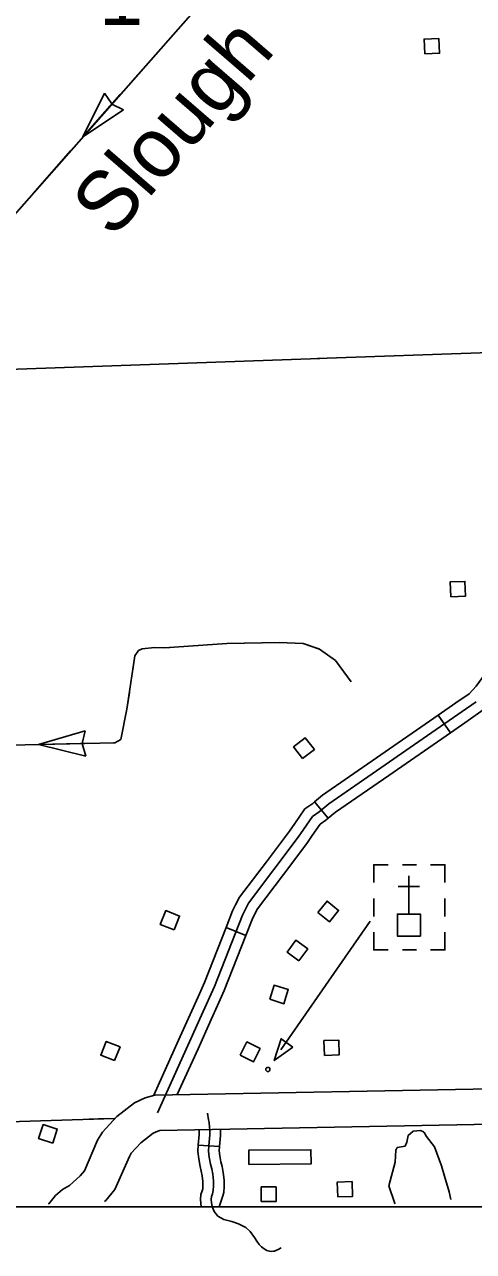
# Model space of a CAD drawing. Extents: x 1671357 to 13005564, y 567358 to 14261451.
# Drawn here: x 12758262.26 to 12758268.24, y 14259853.37 to 14259869.74 of the extents above; entities that cross this region are included whole.
import ezdxf

# ---------------------------------------------------------------- set-up
doc = ezdxf.new("R2010")
doc.units = 0
for name, color, linetype in [('10', 7, 'Continuous'), ('2', 7, 'Continuous'), ('31', 7, 'Continuous'), ('32', 7, 'Continuous'), ('35', 7, 'Continuous'), ('43', 7, 'Continuous'), ('5', 7, 'Continuous'), ('56', 7, 'Continuous')]:
    doc.layers.add(name, color=color, linetype=linetype)

msp = doc.modelspace()

# ---------------------------------------------------------------- linework, layer by layer
at = {"layer": '10'}
for points in [[(12758263.324, 14259854.033), (12758263.343, 14259854.05), (12758263.463, 14259854.196), (12758263.655, 14259854.637), (12758263.68, 14259854.679), (12758263.808, 14259854.82), (12758263.973, 14259854.945), (12758264.036, 14259854.975), (12758264.063, 14259854.983), (12758268.719, 14259855.072), (12758274.49, 14259855.167), (12758274.715, 14259855.191), (12758274.93, 14259855.304), (12758275.071, 14259855.431), (12758275.572, 14259857.551)], [(12758268.71, 14259855.545), (12758263.993, 14259855.456), (12758263.866, 14259855.419), (12758263.724, 14259855.351), (12758263.488, 14259855.171), (12758263.296, 14259854.961), (12758263.232, 14259854.852), (12758263.055, 14259854.446), (12758263, 14259854.379), (12758262.855, 14259854.249), (12758262.764, 14259854.197), (12758262.668, 14259854.114), (12758262.581, 14259854.005), (12758262.579, 14259854.001)]]:
    msp.add_lwpolyline(points, dxfattribs=at)
at = {"layer": '2'}
msp.add_line((12758241.074, 14259853.963), (12758347.684, 14259853.963), dxfattribs=at)
at = {"layer": '31'}
for p, q in [((12758267.772, 14259860.525), (12758267.934, 14259860.292)), ((12758266.125, 14259859.369), (12758266.307, 14259859.151)), ((12758265.708, 14259858.399), (12758265.708, 14259858.399)), ((12758265.208, 14259857.586), (12758264.944, 14259857.69))]:
    msp.add_line(p, q, dxfattribs=at)
for points in [[(12758268.439, 14259861.15), (12758268.419, 14259861.107), (12758268.277, 14259860.913), (12758268.183, 14259860.813), (12758268.009, 14259860.689), (12758267.772, 14259860.525)], [(12758267.934, 14259860.292), (12758268.172, 14259860.457), (12758268.371, 14259860.598), (12758268.495, 14259860.731), (12758268.663, 14259860.96), (12758268.695, 14259861.027)], [(12758268.277, 14259860.706), (12758268.09, 14259860.573), (12758266.316, 14259859.344), (12758266.187, 14259859.237), (12758266.097, 14259859.172), (12758265.977, 14259858.998), (12758265.907, 14259858.897), (12758265.243, 14259858.019), (12758265.197, 14259857.93), (12758265.162, 14259857.856), (12758264.788, 14259856.905), (12758264.617, 14259856.522)], [(12758267.772, 14259860.525), (12758266.95, 14259859.956)], [(12758267.934, 14259860.292), (12758267.112, 14259859.722)], [(12758266.95, 14259859.956), (12758266.23, 14259859.457), (12758266.125, 14259859.369)], [(12758267.112, 14259859.722), (12758266.402, 14259859.231), (12758266.307, 14259859.151)], [(12758265.481, 14259858.57), (12758265.791, 14259858.98), (12758265.86, 14259859.079), (12758265.994, 14259859.274), (12758266.1, 14259859.349), (12758266.125, 14259859.369)], [(12758266.307, 14259859.151), (12758266.274, 14259859.124), (12758266.2, 14259859.071), (12758266.094, 14259858.918), (12758266.022, 14259858.814), (12758265.708, 14259858.399)], [(12758264.944, 14259857.69), (12758265.031, 14259857.913), (12758265.069, 14259857.993), (12758265.122, 14259858.095), (12758265.481, 14259858.57)], [(12758265.708, 14259858.399), (12758265.363, 14259857.943), (12758265.324, 14259857.867), (12758265.292, 14259857.8), (12758265.208, 14259857.586)], [(12758264.944, 14259857.69), (12758264.657, 14259856.96), (12758264.572, 14259856.768)], [(12758265.208, 14259857.586), (12758264.919, 14259856.85), (12758264.831, 14259856.652)], [(12758264.572, 14259856.768), (12758264.488, 14259856.58)], [(12758264.311, 14259856.189), (12758264.488, 14259856.58)], [(12758264.831, 14259856.652), (12758264.747, 14259856.464)], [(12758264.028, 14259855.219), (12758264.617, 14259856.522)], [(12758264.57, 14259856.072), (12758264.747, 14259856.463)], [(12758263.979, 14259855.455), (12758264.311, 14259856.189)], [(12758264.293, 14259855.461), (12758264.57, 14259856.072)]]:
    msp.add_lwpolyline(points, dxfattribs=at)
at = {"layer": '32'}
msp.add_line((12758264.856, 14259854.768), (12758264.573, 14259854.786), dxfattribs=at)
for points in [[(12758265.68, 14259853.415), (12758265.639, 14259853.395), (12758265.608, 14259853.38), (12758265.591, 14259853.374), (12758265.576, 14259853.371), (12758265.551, 14259853.368), (12758265.521, 14259853.371), (12758265.488, 14259853.382), (12758265.451, 14259853.402), (12758265.416, 14259853.431), (12758265.386, 14259853.462), (12758265.356, 14259853.506), (12758265.322, 14259853.554), (12758265.267, 14259853.633), (12758265.208, 14259853.686), (12758265.161, 14259853.712), (12758265.109, 14259853.737), (12758265.019, 14259853.767), (12758264.913, 14259853.795), (12758264.836, 14259853.837), (12758264.784, 14259853.9), (12758264.76, 14259853.967), (12758264.749, 14259854.018), (12758264.745, 14259854.061), (12758264.749, 14259854.1), (12758264.761, 14259854.136), (12758264.772, 14259854.18), (12758264.777, 14259854.242), (12758264.778, 14259854.31), (12758264.767, 14259854.399), (12758264.752, 14259854.472), (12758264.736, 14259854.533), (12758264.719, 14259854.625), (12758264.71, 14259854.706), (12758264.715, 14259854.779), (12758264.727, 14259854.924), (12758264.728, 14259854.99), (12758264.725, 14259855.028), (12758264.719, 14259855.089), (12758264.71, 14259855.123), (12758264.696, 14259855.213)], [(12758264.573, 14259854.786), (12758264.573, 14259854.789), (12758264.585, 14259854.931), (12758264.586, 14259854.993)], [(12758264.856, 14259854.768), (12758264.869, 14259854.916), (12758264.871, 14259854.999)], [(12758264.611, 14259853.963), (12758264.602, 14259854.063), (12758264.609, 14259854.129), (12758264.624, 14259854.176), (12758264.632, 14259854.204), (12758264.635, 14259854.248), (12758264.636, 14259854.302), (12758264.626, 14259854.376), (12758264.614, 14259854.441), (12758264.598, 14259854.501), (12758264.579, 14259854.604), (12758264.568, 14259854.703), (12758264.573, 14259854.786)], [(12758264.854, 14259853.963), (12758264.897, 14259854.097), (12758264.913, 14259854.157), (12758264.919, 14259854.235), (12758264.92, 14259854.318), (12758264.907, 14259854.422), (12758264.891, 14259854.504), (12758264.875, 14259854.564), (12758264.86, 14259854.646), (12758264.853, 14259854.71), (12758264.856, 14259854.768)]]:
    msp.add_lwpolyline(points, dxfattribs=at)
at = {"layer": '35'}
for points in [[(12758267.575, 14259854.964), (12758267.537, 14259854.982), (12758267.438, 14259854.974), (12758267.372, 14259854.918), (12758267.353, 14259854.826), (12758267.331, 14259854.772), (12758267.227, 14259854.755), (12758267.209, 14259854.722), (12758267.197, 14259854.56), (12758267.114, 14259854.243), (12758267.195, 14259854.009), (12758267.191, 14259854.005)], [(12758267.939, 14259854.063), (12758267.918, 14259854.162), (12758267.854, 14259854.373), (12758267.816, 14259854.512), (12758267.721, 14259854.765), (12758267.617, 14259854.901), (12758267.585, 14259854.957), (12758267.575, 14259854.964)]]:
    msp.add_lwpolyline(points, dxfattribs=at)
at = {"layer": '43'}
for p, q in [((12758263.036, 14259868.246), (12758263.325, 14259868.828)), ((12758263.325, 14259868.828), (12758263.421, 14259868.684)), ((12758263.578, 14259868.606), (12758263.423, 14259868.683)), ((12758263.036, 14259868.246), (12758263.578, 14259868.606)), ((12758262.442, 14259860.134), (12758263.066, 14259860.316)), ((12758263.066, 14259860.316), (12758263.025, 14259860.148)), ((12758262.442, 14259860.134), (12758263.073, 14259859.98)), ((12758263.073, 14259859.98), (12758263.025, 14259860.146))]:
    msp.add_line(p, q, dxfattribs=at)
for points in [[(12758266.589, 14259872.281), (12758260.694, 14259865.585), (12758260.462, 14259865.405), (12758260.203, 14259865.244), (12758259.962, 14259865.138), (12758259.827, 14259865.101), (12758259.106, 14259865.033), (12758258.777, 14259865.016), (12758257.851, 14259865.054), (12758257.587, 14259865.116), (12758257.47, 14259865.153), (12758253.89, 14259867.232), (12758253.044, 14259867.635), (12758251.551, 14259868.43), (12758251.309, 14259868.466), (12758251.009, 14259868.39), (12758239.909, 14259866.397), (12758239.657, 14259866.374), (12758239.504, 14259866.384), (12758239.465, 14259866.393)], [(12758264.193, 14259869.559), (12758263.697, 14259868.996)], [(12758263.532, 14259868.809), (12758263.036, 14259868.246)], [(12758262.871, 14259868.058), (12758262.623, 14259867.776)], [(12758262.623, 14259867.776), (12758262.376, 14259867.495)], [(12758266.611, 14259860.97), (12758266.401, 14259861.256), (12758266.19, 14259861.406), (12758265.973, 14259861.481), (12758265.653, 14259861.495), (12758264.952, 14259861.483), (12758264.122, 14259861.424), (12758263.988, 14259861.428), (12758263.824, 14259861.41), (12758263.777, 14259861.388), (12758263.729, 14259861.317), (12758263.623, 14259860.608), (12758263.54, 14259860.202), (12758263.462, 14259860.157), (12758255.478, 14259859.977)], [(12758265.191, 14259861.487), (12758264.952, 14259861.483), (12758264.443, 14259861.447)], [(12758266.179, 14259861.41), (12758265.973, 14259861.481), (12758265.653, 14259861.495), (12758265.441, 14259861.491)], [(12758264.193, 14259861.429), (12758264.122, 14259861.424), (12758263.988, 14259861.428), (12758263.824, 14259861.41), (12758263.777, 14259861.388), (12758263.729, 14259861.317), (12758263.693, 14259861.078)], [(12758266.611, 14259860.97), (12758266.401, 14259861.256), (12758266.384, 14259861.268)], [(12758263.656, 14259860.831), (12758263.623, 14259860.608), (12758263.54, 14259860.202), (12758263.462, 14259860.157), (12758263.441, 14259860.157)], [(12758263.191, 14259860.151), (12758262.442, 14259860.134)]]:
    msp.add_lwpolyline(points, dxfattribs=at)
at = {"layer": '5'}
for points in [[(12758266.162, 14259865.286), (12758268.459, 14259865.366), (12758270.694, 14259865.434)], [(12758259.508, 14259865.053), (12758266.196, 14259865.287)], [(12758266.162, 14259865.286), (12758266.196, 14259865.287)], [(12758263.457, 14259855.144), (12758258.808, 14259854.995)], [(12758263.359, 14259855.141), (12758263.12, 14259855.133)]]:
    msp.add_lwpolyline(points, dxfattribs=at)
at = {"layer": '56'}
for p, q in [((12758267.483, 14259858.529), (12758267.294, 14259858.529)), ((12758267.381, 14259858.382), (12758267.381, 14259857.872)), ((12758267.239, 14259858.24), (12758267.524, 14259858.24)), ((12758266.914, 14259858.077), (12758266.914, 14259857.841)), ((12758267.861, 14259857.961), (12758267.861, 14259858.077)), ((12758267.861, 14259857.961), (12758267.861, 14259857.841)), ((12758267.294, 14259857.392), (12758267.483, 14259857.392))]:
    msp.add_line(p, q, dxfattribs=at)
for points in [[(12758267.593, 14259869.353), (12758267.585, 14259869.55), (12758267.782, 14259869.558), (12758267.79, 14259869.361)], [(12758267.939, 14259862.107), (12758267.931, 14259862.304), (12758268.129, 14259862.312), (12758268.137, 14259862.115)], [(12758265.965, 14259859.948), (12758265.843, 14259860.103), (12758265.998, 14259860.225), (12758266.121, 14259860.07)], [(12758266.168, 14259857.891), (12758266.291, 14259858.044), (12758266.445, 14259857.921), (12758266.322, 14259857.767)], [(12758264.25, 14259857.661), (12758264.067, 14259857.734), (12758264.14, 14259857.918), (12758264.324, 14259857.845)], [(12758267.534, 14259857.577), (12758267.534, 14259857.872), (12758267.228, 14259857.872), (12758267.228, 14259857.577)], [(12758265.915, 14259857.247), (12758265.757, 14259857.365), (12758265.876, 14259857.524), (12758266.034, 14259857.406)], [(12758265.527, 14259856.734), (12758265.585, 14259856.922), (12758265.774, 14259856.864), (12758265.716, 14259856.675)], [(12758265.834, 14259856.096), (12758265.677, 14259856.208), (12758265.587, 14259855.916)], [(12758263.457, 14259855.915), (12758263.274, 14259855.988), (12758263.347, 14259856.171), (12758263.531, 14259856.098)], [(12758265.133, 14259855.988), (12758265.221, 14259856.164), (12758265.398, 14259856.076), (12758265.31, 14259855.9)], [(12758266.256, 14259855.985), (12758266.248, 14259856.182), (12758266.446, 14259856.19), (12758266.453, 14259855.993)], [(12758262.633, 14259854.813), (12758262.445, 14259854.874), (12758262.506, 14259855.062), (12758262.694, 14259855.002)], [(12758265.248, 14259854.529), (12758265.246, 14259854.718), (12758266.075, 14259854.726), (12758266.077, 14259854.536)], [(12758266.434, 14259854.096), (12758266.426, 14259854.293), (12758266.624, 14259854.3), (12758266.631, 14259854.103)], [(12758265.413, 14259854.033), (12758265.413, 14259854.23), (12758265.611, 14259854.23), (12758265.611, 14259854.033)]]:
    msp.add_lwpolyline(points, close=True, dxfattribs=at)
for points in [[(12758267.103, 14259858.529), (12758266.914, 14259858.529), (12758266.914, 14259858.292)], [(12758267.671, 14259858.529), (12758267.861, 14259858.529), (12758267.861, 14259858.292)], [(12758266.863, 14259857.775), (12758265.676, 14259856.061)], [(12758266.914, 14259857.629), (12758266.914, 14259857.392), (12758267.103, 14259857.392)], [(12758267.671, 14259857.392), (12758267.861, 14259857.392), (12758267.861, 14259857.629)]]:
    msp.add_lwpolyline(points, dxfattribs=at)
msp.add_circle((12758265.501, 14259855.797), 0.0284, dxfattribs=at)

# ---------------------------------------------------------------- texts
at = {"layer": '43'}
msp.add_text('Slough', height=0.8001, rotation=49.114, dxfattribs=at).set_placement((12758263.435, 14259866.87))
at = {"layer": '5'}
msp.add_text('1', height=0.8, dxfattribs=at).set_placement((12758263.247, 14259869.737))

doc.saveas('drawing.dxf')
